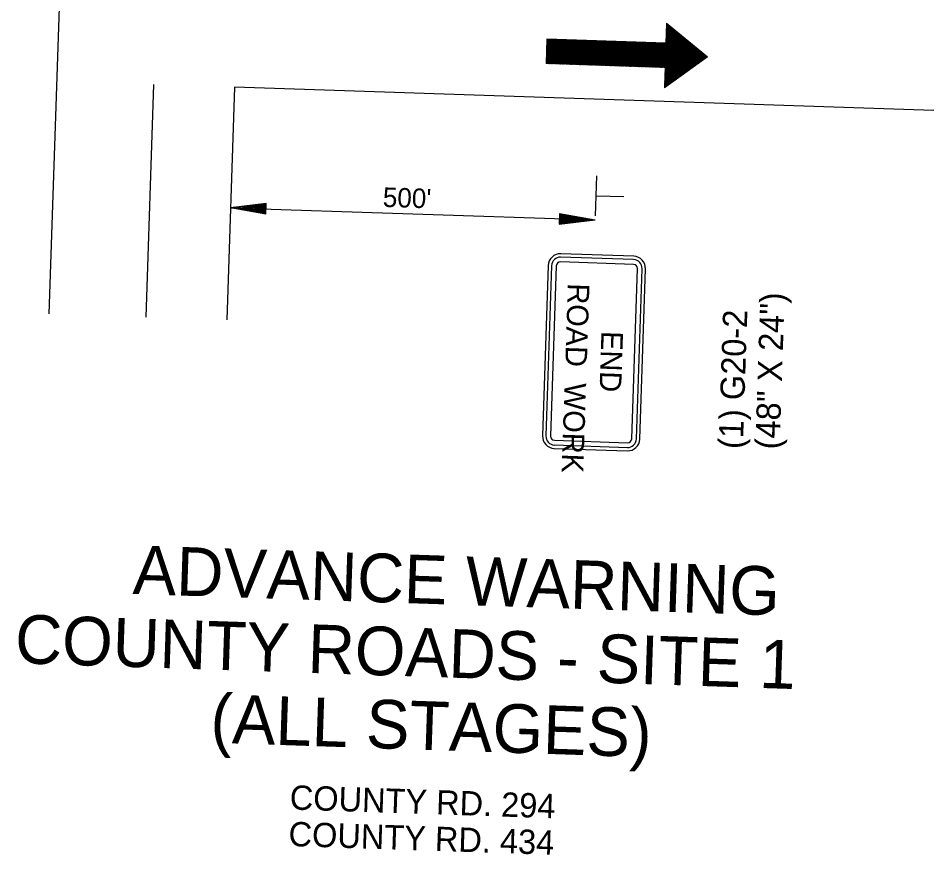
# Model space of a CAD drawing. Extents: x 977269 to 979191, y 1525946 to 1526973.
# Drawn here: x 978082.7 to 978308.5, y 1525973.6 to 1526179.9 of the extents above; entities that cross this region are included whole.
import ezdxf

# ---------------------------------------------------------------- set-up
doc = ezdxf.new("R2010")
doc.units = 0
for name, color, linetype in [('BDR_Plan Profile Grid 4', 7, 'Continuous'), ('R_Border', 7, 'Continuous'), ('STAMP', 7, 'Continuous'), ('STAMP_PP', 7, 'Continuous')]:
    doc.layers.add(name, color=color, linetype=linetype)

msp = doc.modelspace()

# ---------------------------------------------------------------- linework, layer by layer
at = {"layer": 'BDR_Plan Profile Grid 4'}
for p, q in [((978242.59, 1526178.69), (978242.42, 1526173.7)), ((978242.58, 1526178.53), (978242.68, 1526178.62)), ((978242.58, 1526178.39), (978242.75, 1526178.55)), ((978242.59, 1526178.69), (978252.68, 1526170.37)), ((978242.59, 1526178.67), (978242.6, 1526178.68)), ((978236.36, 1526167.92), (978245.4, 1526176.37)), ((978236.51, 1526167.91), (978245.48, 1526176.31)), ((978242.42, 1526173.72), (978245.32, 1526176.43)), ((978242.43, 1526174), (978245.17, 1526176.56)), ((978242.43, 1526173.86), (978245.24, 1526176.5)), ((978242.44, 1526174.29), (978245.01, 1526176.69)), ((978242.44, 1526174.15), (978245.09, 1526176.63)), ((978242.45, 1526174.57), (978244.85, 1526176.82)), ((978242.45, 1526174.43), (978244.93, 1526176.75)), ((978242.46, 1526174.85), (978244.7, 1526176.95)), ((978242.46, 1526174.71), (978244.78, 1526176.88)), ((978242.47, 1526175.28), (978244.47, 1526177.14)), ((978242.47, 1526175.14), (978244.54, 1526177.08)), ((978242.47, 1526174.99), (978244.62, 1526177.01)), ((978242.48, 1526175.56), (978244.31, 1526177.27)), ((978242.48, 1526175.42), (978244.39, 1526177.2)), ((978242.49, 1526175.84), (978244.15, 1526177.4)), ((978242.49, 1526175.7), (978244.23, 1526177.33)), ((978242.5, 1526176.12), (978244, 1526177.52)), ((978242.5, 1526175.98), (978244.08, 1526177.46)), ((978242.51, 1526176.41), (978243.84, 1526177.65)), ((978242.51, 1526176.27), (978243.92, 1526177.59)), ((978242.52, 1526176.69), (978243.69, 1526177.78)), ((978242.52, 1526176.55), (978243.77, 1526177.72)), ((978242.53, 1526176.97), (978243.53, 1526177.91)), ((978242.53, 1526176.83), (978243.61, 1526177.85)), ((978242.54, 1526177.26), (978243.38, 1526178.04)), ((978242.54, 1526177.11), (978243.45, 1526177.97)), ((978242.55, 1526177.68), (978243.14, 1526178.23)), ((978242.55, 1526177.54), (978243.22, 1526178.17)), ((978242.55, 1526177.4), (978243.3, 1526178.1)), ((978242.56, 1526177.96), (978242.99, 1526178.36)), ((978242.56, 1526177.82), (978243.07, 1526178.29)), ((978242.57, 1526178.24), (978242.83, 1526178.49)), ((978242.57, 1526178.1), (978242.91, 1526178.42)), ((978213.09, 1526174.68), (978212.89, 1526168.7)), ((978212.9, 1526168.83), (978218.94, 1526174.49)), ((978212.9, 1526168.97), (978218.8, 1526174.49)), ((978212.9, 1526168.7), (978219.08, 1526174.48)), ((978212.91, 1526169.4), (978218.38, 1526174.51)), ((978212.91, 1526169.11), (978218.66, 1526174.5)), ((978212.91, 1526169.26), (978218.52, 1526174.5)), ((978212.92, 1526169.54), (978218.23, 1526174.51)), ((978212.92, 1526169.68), (978218.09, 1526174.51)), ((978212.93, 1526169.82), (978217.95, 1526174.52)), ((978212.93, 1526169.96), (978217.81, 1526174.52)), ((978212.94, 1526170.1), (978217.67, 1526174.53)), ((978212.94, 1526170.25), (978217.53, 1526174.53)), ((978212.95, 1526170.39), (978217.39, 1526174.54)), ((978212.95, 1526170.53), (978217.24, 1526174.54)), ((978212.96, 1526170.67), (978217.1, 1526174.55)), ((978212.96, 1526170.81), (978216.96, 1526174.55)), ((978212.97, 1526170.95), (978216.82, 1526174.56)), ((978212.97, 1526171.09), (978216.68, 1526174.56)), ((978212.98, 1526171.23), (978216.54, 1526174.57)), ((978212.98, 1526171.38), (978216.4, 1526174.57)), ((978212.99, 1526171.8), (978215.97, 1526174.59)), ((978212.99, 1526171.52), (978216.26, 1526174.58)), ((978212.99, 1526171.66), (978216.11, 1526174.58)), ((978213, 1526171.94), (978215.83, 1526174.59)), ((978213, 1526172.08), (978215.69, 1526174.59)), ((978213.01, 1526172.22), (978215.55, 1526174.6)), ((978213.01, 1526172.37), (978215.41, 1526174.6)), ((978213.02, 1526172.51), (978215.27, 1526174.61)), ((978213.02, 1526172.65), (978215.12, 1526174.61)), ((978213.03, 1526172.79), (978214.98, 1526174.62)), ((978213.03, 1526172.93), (978214.84, 1526174.62)), ((978213.04, 1526173.07), (978214.7, 1526174.63)), ((978213.04, 1526173.21), (978214.56, 1526174.63)), ((978213.04, 1526168.7), (978219.22, 1526174.48)), ((978213.05, 1526173.35), (978214.42, 1526174.64)), ((978213.05, 1526173.5), (978214.28, 1526174.64)), ((978213.06, 1526173.64), (978214.13, 1526174.65)), ((978213.06, 1526173.78), (978213.99, 1526174.65)), ((978213.07, 1526173.92), (978213.85, 1526174.66)), ((978213.07, 1526174.06), (978213.71, 1526174.66)), ((978213.08, 1526174.2), (978213.57, 1526174.67)), ((978213.08, 1526174.34), (978213.43, 1526174.67)), ((978213.08, 1526174.49), (978213.29, 1526174.67)), ((978242.42, 1526173.7), (978213.09, 1526174.68)), ((978213.09, 1526174.63), (978213.15, 1526174.68)), ((978213.18, 1526168.69), (978219.36, 1526174.47)), ((978213.33, 1526168.69), (978219.51, 1526174.47)), ((978213.47, 1526168.68), (978219.65, 1526174.46)), ((978213.61, 1526168.68), (978219.79, 1526174.46)), ((978213.75, 1526168.67), (978219.93, 1526174.45)), ((978213.89, 1526168.67), (978220.07, 1526174.45)), ((978214.03, 1526168.66), (978220.21, 1526174.44)), ((978214.17, 1526168.66), (978220.35, 1526174.44)), ((978214.31, 1526168.65), (978220.5, 1526174.43)), ((978214.46, 1526168.65), (978220.64, 1526174.43)), ((978214.6, 1526168.64), (978220.78, 1526174.43)), ((978214.74, 1526168.64), (978220.92, 1526174.42)), ((978214.88, 1526168.63), (978221.06, 1526174.42)), ((978215.02, 1526168.63), (978221.2, 1526174.41)), ((978215.16, 1526168.62), (978221.34, 1526174.41)), ((978215.3, 1526168.62), (978221.48, 1526174.4)), ((978215.45, 1526168.61), (978221.63, 1526174.4)), ((978215.59, 1526168.61), (978221.77, 1526174.39)), ((978215.73, 1526168.61), (978221.91, 1526174.39)), ((978215.87, 1526168.6), (978222.05, 1526174.38)), ((978216.01, 1526168.6), (978222.19, 1526174.38)), ((978216.15, 1526168.59), (978222.33, 1526174.37)), ((978216.29, 1526168.59), (978222.47, 1526174.37)), ((978216.43, 1526168.58), (978222.62, 1526174.36)), ((978216.58, 1526168.58), (978222.76, 1526174.36)), ((978216.72, 1526168.57), (978222.9, 1526174.35)), ((978216.86, 1526168.57), (978223.04, 1526174.35)), ((978217, 1526168.56), (978223.18, 1526174.34)), ((978217.14, 1526168.56), (978223.32, 1526174.34)), ((978217.28, 1526168.55), (978223.46, 1526174.34)), ((978217.42, 1526168.55), (978223.6, 1526174.33)), ((978217.57, 1526168.54), (978223.75, 1526174.33)), ((978217.71, 1526168.54), (978223.89, 1526174.32)), ((978217.85, 1526168.53), (978224.03, 1526174.32)), ((978217.99, 1526168.53), (978224.17, 1526174.31)), ((978218.13, 1526168.53), (978224.31, 1526174.31)), ((978218.27, 1526168.52), (978224.45, 1526174.3)), ((978218.41, 1526168.52), (978224.59, 1526174.3)), ((978218.55, 1526168.51), (978224.74, 1526174.29)), ((978218.7, 1526168.51), (978224.88, 1526174.29)), ((978218.84, 1526168.5), (978225.02, 1526174.28)), ((978218.98, 1526168.5), (978225.16, 1526174.28)), ((978219.12, 1526168.49), (978225.3, 1526174.27)), ((978219.26, 1526168.49), (978225.44, 1526174.27)), ((978219.4, 1526168.48), (978225.58, 1526174.26)), ((978219.54, 1526168.48), (978225.73, 1526174.26)), ((978219.69, 1526168.47), (978225.87, 1526174.26)), ((978219.83, 1526168.47), (978226.01, 1526174.25)), ((978219.97, 1526168.46), (978226.15, 1526174.25)), ((978220.11, 1526168.46), (978226.29, 1526174.24)), ((978220.25, 1526168.45), (978226.43, 1526174.24)), ((978220.39, 1526168.45), (978226.57, 1526174.23)), ((978220.53, 1526168.45), (978226.71, 1526174.23)), ((978220.68, 1526168.44), (978226.86, 1526174.22)), ((978220.82, 1526168.44), (978227, 1526174.22)), ((978220.96, 1526168.43), (978227.14, 1526174.21)), ((978221.1, 1526168.43), (978227.28, 1526174.21)), ((978221.24, 1526168.42), (978227.42, 1526174.2)), ((978221.38, 1526168.42), (978227.56, 1526174.2)), ((978221.52, 1526168.41), (978227.7, 1526174.19)), ((978221.66, 1526168.41), (978227.85, 1526174.19)), ((978221.81, 1526168.4), (978227.99, 1526174.18)), ((978221.95, 1526168.4), (978228.13, 1526174.18)), ((978222.09, 1526168.39), (978228.27, 1526174.18)), ((978222.23, 1526168.39), (978228.41, 1526174.17)), ((978222.37, 1526168.38), (978228.55, 1526174.17)), ((978222.51, 1526168.38), (978228.69, 1526174.16)), ((978222.65, 1526168.37), (978228.83, 1526174.16)), ((978222.8, 1526168.37), (978228.98, 1526174.15)), ((978222.94, 1526168.37), (978229.12, 1526174.15)), ((978223.08, 1526168.36), (978229.26, 1526174.14)), ((978223.22, 1526168.36), (978229.4, 1526174.14)), ((978223.36, 1526168.35), (978229.54, 1526174.13)), ((978223.5, 1526168.35), (978229.68, 1526174.13)), ((978223.64, 1526168.34), (978229.82, 1526174.12)), ((978223.78, 1526168.34), (978229.97, 1526174.12)), ((978223.93, 1526168.33), (978230.11, 1526174.11)), ((978224.07, 1526168.33), (978230.25, 1526174.11)), ((978224.21, 1526168.32), (978230.39, 1526174.1)), ((978224.35, 1526168.32), (978230.53, 1526174.1)), ((978224.49, 1526168.31), (978230.67, 1526174.1)), ((978224.63, 1526168.31), (978230.81, 1526174.09)), ((978224.77, 1526168.3), (978230.95, 1526174.09)), ((978224.92, 1526168.3), (978231.1, 1526174.08)), ((978225.06, 1526168.29), (978231.24, 1526174.08)), ((978225.2, 1526168.29), (978231.38, 1526174.07)), ((978225.34, 1526168.29), (978231.52, 1526174.07)), ((978225.48, 1526168.28), (978231.66, 1526174.06)), ((978225.62, 1526168.28), (978231.8, 1526174.06)), ((978225.76, 1526168.27), (978231.94, 1526174.05)), ((978225.9, 1526168.27), (978232.09, 1526174.05)), ((978226.05, 1526168.26), (978232.23, 1526174.04)), ((978226.19, 1526168.26), (978232.37, 1526174.04)), ((978226.33, 1526168.25), (978232.51, 1526174.03)), ((978226.47, 1526168.25), (978232.65, 1526174.03)), ((978226.61, 1526168.24), (978232.79, 1526174.02)), ((978226.75, 1526168.24), (978232.93, 1526174.02)), ((978226.89, 1526168.23), (978233.07, 1526174.02)), ((978227.04, 1526168.23), (978233.22, 1526174.01)), ((978227.18, 1526168.22), (978233.36, 1526174.01)), ((978227.32, 1526168.22), (978233.5, 1526174)), ((978227.46, 1526168.21), (978233.64, 1526174)), ((978227.6, 1526168.21), (978233.78, 1526173.99)), ((978236.65, 1526167.91), (978245.55, 1526176.24)), ((978236.79, 1526167.9), (978245.63, 1526176.18)), ((978236.93, 1526167.9), (978245.71, 1526176.11)), ((978237.07, 1526167.89), (978245.79, 1526176.05)), ((978237.21, 1526167.89), (978245.87, 1526175.98)), ((978237.35, 1526167.88), (978245.94, 1526175.92)), ((978237.49, 1526167.88), (978246.02, 1526175.86)), ((978237.64, 1526167.87), (978246.1, 1526175.79)), ((978237.78, 1526167.87), (978246.18, 1526175.73)), ((978237.92, 1526167.87), (978246.25, 1526175.66)), ((978238.06, 1526167.86), (978246.33, 1526175.6)), ((978238.2, 1526167.86), (978246.41, 1526175.54)), ((978238.34, 1526167.85), (978246.49, 1526175.47)), ((978238.48, 1526167.85), (978246.57, 1526175.41)), ((978238.63, 1526167.84), (978246.64, 1526175.34)), ((978238.77, 1526167.84), (978246.72, 1526175.28)), ((978238.91, 1526167.83), (978246.8, 1526175.21)), ((978239.05, 1526167.83), (978246.88, 1526175.15)), ((978239.19, 1526167.82), (978246.96, 1526175.09)), ((978239.33, 1526167.82), (978247.03, 1526175.02)), ((978239.47, 1526167.81), (978247.11, 1526174.96)), ((978239.61, 1526167.81), (978247.19, 1526174.89)), ((978239.76, 1526167.8), (978247.27, 1526174.83)), ((978239.9, 1526167.8), (978247.34, 1526174.77)), ((978240.04, 1526167.79), (978247.42, 1526174.7)), ((978240.18, 1526167.79), (978247.5, 1526174.64)), ((978240.32, 1526167.79), (978247.58, 1526174.57)), ((978240.46, 1526167.78), (978247.66, 1526174.51)), ((978240.6, 1526167.78), (978247.73, 1526174.44)), ((978240.75, 1526167.77), (978247.81, 1526174.38)), ((978240.89, 1526167.77), (978247.89, 1526174.32)), ((978241.03, 1526167.76), (978247.97, 1526174.25)), ((978241.17, 1526167.76), (978248.04, 1526174.19)), ((978241.31, 1526167.75), (978248.12, 1526174.12)), ((978241.45, 1526167.75), (978248.2, 1526174.06)), ((978241.59, 1526167.74), (978248.28, 1526174)), ((978227.74, 1526168.2), (978233.92, 1526173.99)), ((978227.88, 1526168.2), (978234.06, 1526173.98)), ((978228.02, 1526168.2), (978234.21, 1526173.98)), ((978228.17, 1526168.19), (978234.35, 1526173.97)), ((978228.31, 1526168.19), (978234.49, 1526173.97)), ((978228.45, 1526168.18), (978234.63, 1526173.96)), ((978228.59, 1526168.18), (978234.77, 1526173.96)), ((978228.73, 1526168.17), (978234.91, 1526173.95)), ((978228.87, 1526168.17), (978235.05, 1526173.95)), ((978229.01, 1526168.16), (978235.2, 1526173.94)), ((978229.16, 1526168.16), (978235.34, 1526173.94)), ((978229.3, 1526168.15), (978235.48, 1526173.93)), ((978229.44, 1526168.15), (978235.62, 1526173.93)), ((978229.58, 1526168.14), (978235.76, 1526173.93)), ((978229.72, 1526168.14), (978235.9, 1526173.92)), ((978229.86, 1526168.13), (978236.04, 1526173.92)), ((978230, 1526168.13), (978236.18, 1526173.91)), ((978230.15, 1526168.12), (978236.33, 1526173.91)), ((978230.29, 1526168.12), (978236.47, 1526173.9)), ((978230.43, 1526168.12), (978236.61, 1526173.9)), ((978230.57, 1526168.11), (978236.75, 1526173.89)), ((978230.71, 1526168.11), (978236.89, 1526173.89)), ((978230.85, 1526168.1), (978237.03, 1526173.88)), ((978230.99, 1526168.1), (978237.17, 1526173.88)), ((978231.13, 1526168.09), (978237.32, 1526173.87)), ((978231.28, 1526168.09), (978237.46, 1526173.87)), ((978231.42, 1526168.08), (978237.6, 1526173.86)), ((978231.56, 1526168.08), (978237.74, 1526173.86)), ((978231.7, 1526168.07), (978237.88, 1526173.85)), ((978231.84, 1526168.07), (978238.02, 1526173.85)), ((978231.98, 1526168.06), (978238.16, 1526173.85)), ((978232.12, 1526168.06), (978238.3, 1526173.84)), ((978232.27, 1526168.05), (978238.45, 1526173.84)), ((978232.41, 1526168.05), (978238.59, 1526173.83)), ((978232.55, 1526168.04), (978238.73, 1526173.83)), ((978232.69, 1526168.04), (978238.87, 1526173.82)), ((978232.83, 1526168.04), (978239.01, 1526173.82)), ((978232.97, 1526168.03), (978239.15, 1526173.81)), ((978233.11, 1526168.03), (978239.29, 1526173.81)), ((978233.25, 1526168.02), (978239.44, 1526173.8)), ((978233.4, 1526168.02), (978239.58, 1526173.8)), ((978233.54, 1526168.01), (978239.72, 1526173.79)), ((978233.68, 1526168.01), (978239.86, 1526173.79)), ((978233.82, 1526168), (978240, 1526173.78)), ((978233.96, 1526168), (978240.14, 1526173.78)), ((978234.1, 1526167.99), (978240.28, 1526173.77)), ((978234.24, 1526167.99), (978240.42, 1526173.77)), ((978234.39, 1526167.98), (978240.57, 1526173.77)), ((978234.53, 1526167.98), (978240.71, 1526173.76)), ((978234.67, 1526167.97), (978240.85, 1526173.76)), ((978234.81, 1526167.97), (978240.99, 1526173.75)), ((978234.95, 1526167.96), (978241.13, 1526173.75)), ((978235.09, 1526167.96), (978241.27, 1526173.74)), ((978235.23, 1526167.96), (978241.41, 1526173.74)), ((978235.37, 1526167.95), (978241.56, 1526173.73)), ((978235.52, 1526167.95), (978241.7, 1526173.73)), ((978235.66, 1526167.94), (978241.84, 1526173.72)), ((978235.8, 1526167.94), (978241.98, 1526173.72)), ((978235.94, 1526167.93), (978242.12, 1526173.71)), ((978236.08, 1526167.93), (978242.26, 1526173.71)), ((978236.22, 1526167.92), (978242.4, 1526173.7)), ((978241.74, 1526167.74), (978248.36, 1526173.93)), ((978241.88, 1526167.73), (978248.43, 1526173.87)), ((978242.02, 1526167.73), (978248.51, 1526173.8)), ((978242.08, 1526163.55), (978250.92, 1526171.81)), ((978242.08, 1526163.4), (978251, 1526171.75)), ((978242.09, 1526163.83), (978250.77, 1526171.94)), ((978242.09, 1526163.69), (978250.84, 1526171.88)), ((978242.1, 1526164.11), (978250.61, 1526172.07)), ((978242.1, 1526163.97), (978250.69, 1526172.01)), ((978242.11, 1526164.39), (978250.46, 1526172.2)), ((978242.11, 1526164.25), (978250.53, 1526172.13)), ((978242.12, 1526164.68), (978250.3, 1526172.33)), ((978242.12, 1526164.53), (978250.38, 1526172.26)), ((978242.13, 1526164.96), (978250.14, 1526172.46)), ((978242.13, 1526164.82), (978250.22, 1526172.39)), ((978242.14, 1526165.38), (978249.91, 1526172.65)), ((978242.14, 1526165.24), (978249.99, 1526172.58)), ((978242.14, 1526165.1), (978250.07, 1526172.52)), ((978242.15, 1526165.67), (978249.76, 1526172.78)), ((978242.15, 1526165.52), (978249.83, 1526172.71)), ((978242.16, 1526167.72), (978248.59, 1526173.74)), ((978242.16, 1526165.95), (978249.6, 1526172.9)), ((978242.16, 1526165.81), (978249.68, 1526172.84)), ((978242.17, 1526166.23), (978249.44, 1526173.03)), ((978242.17, 1526166.09), (978249.52, 1526172.97)), ((978242.18, 1526166.51), (978249.29, 1526173.16)), ((978242.18, 1526166.37), (978249.37, 1526173.1)), ((978242.19, 1526166.8), (978249.13, 1526173.29)), ((978242.19, 1526166.65), (978249.21, 1526173.23)), ((978242.2, 1526167.08), (978248.98, 1526173.42)), ((978242.2, 1526166.94), (978249.06, 1526173.35)), ((978242.21, 1526167.36), (978248.82, 1526173.55)), ((978242.21, 1526167.22), (978248.9, 1526173.48)), ((978242.22, 1526167.64), (978248.67, 1526173.67)), ((978242.22, 1526167.5), (978248.74, 1526173.61)), ((978242.06, 1526162.98), (978251.23, 1526171.56)), ((978242.06, 1526162.84), (978251.31, 1526171.49)), ((978252.68, 1526170.37), (978242.06, 1526162.74)), ((978242.07, 1526163.26), (978251.08, 1526171.69)), ((978242.07, 1526163.12), (978251.16, 1526171.62)), ((978242.24, 1526162.87), (978251.39, 1526171.43)), ((978242.87, 1526163.32), (978251.47, 1526171.36)), ((978243.5, 1526163.77), (978251.54, 1526171.3)), ((978244.13, 1526164.23), (978251.62, 1526171.24)), ((978244.76, 1526164.68), (978251.7, 1526171.17)), ((978245.39, 1526165.13), (978251.78, 1526171.11)), ((978246.02, 1526165.59), (978251.86, 1526171.04)), ((978246.65, 1526166.04), (978251.93, 1526170.98)), ((978247.28, 1526166.49), (978252.01, 1526170.92)), ((978247.92, 1526166.95), (978252.09, 1526170.85)), ((978248.55, 1526167.4), (978252.17, 1526170.79)), ((978249.18, 1526167.85), (978252.24, 1526170.72)), ((978249.81, 1526168.31), (978252.32, 1526170.66)), ((978250.44, 1526168.76), (978252.4, 1526170.59)), ((978251.07, 1526169.21), (978252.48, 1526170.53)), ((978251.7, 1526169.67), (978252.56, 1526170.47)), ((978252.33, 1526170.12), (978252.63, 1526170.4)), ((978242.22, 1526167.72), (978212.89, 1526168.7)), ((978242.22, 1526167.72), (978242.06, 1526162.74))]:
    msp.add_line(p, q, dxfattribs=at)
at = {"layer": 'STAMP'}
for p, q in [((978096.33, 1526289.59), (978090.24, 1526107)), ((978116.08, 1526163.53), (978114.17, 1526106.2)), ((978136.02, 1526162.86), (978134.11, 1526105.54)), ((978308.46, 1526157.11), (978136.02, 1526162.86)), ((978225.32, 1526141.05), (978224.99, 1526131.15)), ((978225.3, 1526136.12), (978232.05, 1526135.89)), ((978143.87, 1526134.18), (978135.03, 1526133.15)), ((978143.87, 1526133.96), (978136.5, 1526133.1)), ((978143.86, 1526133.73), (978138.02, 1526133.05)), ((978143.85, 1526133.51), (978139.48, 1526133)), ((978143.79, 1526131.54), (978143.87, 1526134.18)), ((978135.03, 1526133.15), (978224.96, 1526130.15)), ((978143.79, 1526131.54), (978135.03, 1526133.15)), ((978143.79, 1526131.76), (978136.5, 1526133.1)), ((978143.8, 1526131.98), (978138.02, 1526133.05)), ((978143.81, 1526132.2), (978139.48, 1526133)), ((978143.84, 1526133.29), (978140.97, 1526132.95)), ((978143.82, 1526132.43), (978140.97, 1526132.95)), ((978143.84, 1526133.06), (978142.44, 1526132.9)), ((978143.82, 1526132.65), (978142.44, 1526132.9)), ((978216.21, 1526131.76), (978216.12, 1526129.13)), ((978216.19, 1526131.1), (978220.52, 1526130.3)), ((978216.2, 1526131.54), (978223.5, 1526130.2)), ((978216.2, 1526131.32), (978221.98, 1526130.25)), ((978216.21, 1526131.76), (978224.96, 1526130.15)), ((978216.12, 1526129.13), (978224.96, 1526130.15)), ((978216.13, 1526129.35), (978223.5, 1526130.2)), ((978216.14, 1526129.57), (978221.98, 1526130.25)), ((978216.15, 1526130.01), (978219.03, 1526130.35)), ((978216.15, 1526129.79), (978220.52, 1526130.3)), ((978216.16, 1526130.24), (978217.56, 1526130.4)), ((978216.18, 1526130.87), (978219.03, 1526130.35)), ((978216.18, 1526130.65), (978217.56, 1526130.4))]:
    msp.add_line(p, q, dxfattribs=at)
at = {"layer": 'STAMP_PP'}
for p, q in [((978234.45, 1526120.36), (978216.46, 1526120.96)), ((978234.48, 1526121.2), (978216.49, 1526121.8)), ((978213.39, 1526118.9), (978211.99, 1526076.92)), ((978214.22, 1526118.87), (978212.82, 1526076.89)), ((978215.39, 1526118.83), (978213.99, 1526076.86)), ((978234.41, 1526119.2), (978216.42, 1526119.8)), ((978233.98, 1526076.19), (978235.38, 1526118.17)), ((978235.14, 1526076.15), (978236.54, 1526118.13)), ((978235.98, 1526076.12), (978237.38, 1526118.1)), ((978214.95, 1526075.82), (978232.94, 1526075.22)), ((978214.89, 1526073.82), (978232.88, 1526073.22)), ((978214.92, 1526074.66), (978232.91, 1526074.06))]:
    msp.add_line(p, q, dxfattribs=at)
for centre, radius, start, end in [((978216.39, 1526118.8), 3, 88.0901, 178.0901), ((978216.39, 1526118.8), 2.17, 88.0901, 178.0901), ((978234.38, 1526118.2), 2.17, 358.0901, 88.0901), ((978234.38, 1526118.2), 3, 358.0901, 88.0901), ((978216.39, 1526118.8), 1, 88.0901, 178.0901), ((978234.38, 1526118.2), 1, 358.0901, 88.0901), ((978214.99, 1526076.82), 3, 178.0901, 268.0901), ((978214.99, 1526076.82), 2.17, 178.0901, 268.0901), ((978214.99, 1526076.82), 1, 178.0901, 268.0901), ((978232.98, 1526076.22), 3, 268.0901, 358.0901), ((978232.98, 1526076.22), 2.17, 268.0901, 358.0901), ((978232.98, 1526076.22), 1, 268.0901, 358.0901)]:
    msp.add_arc(centre, radius, start, end, dxfattribs=at)

# ---------------------------------------------------------------- texts
at = {"layer": 'R_Border'}
for s, height, rotation, p in [("500'", 4.8, 358.0901, (978172.55, 1526133.39)), ('(48" X 24")', 6, 88.0901, (978270.44, 1526073.51)), ('(1) G20-2', 6, 88.0901, (978261.38, 1526073.6)), ('ADVANCE WARNING', 12, 358.0901, (978110.83, 1526037.93)), ('COUNTY ROADS - SITE 1', 12, 358.0901, (978081.76, 1526020.89)), ('(ALL STAGES)', 12, 358.0901, (978129.98, 1526001.27)), ('COUNTY RD. 294', 6, 358.0901, (978149.58, 1525984.79)), ('COUNTY RD. 434', 6, 358.0901, (978149.28, 1525975.79))]:
    msp.add_text(s, height=height, rotation=rotation, dxfattribs=at).set_placement(p)
at = {"layer": 'STAMP_PP'}
for s, p in [('ROAD  WORK', (978218.25, 1526114.59)), ('END', (978226.53, 1526102.81))]:
    msp.add_text(s, height=5.333, rotation=268.0901, dxfattribs=at).set_placement(p)

doc.saveas('drawing.dxf')
